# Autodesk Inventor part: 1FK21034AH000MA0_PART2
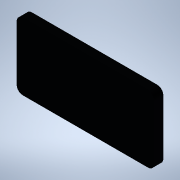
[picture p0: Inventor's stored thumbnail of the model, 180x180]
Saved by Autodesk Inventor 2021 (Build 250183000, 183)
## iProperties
Created: 2025-04
Part Number: 1FK21034AH000MA0_PART2
Material: Generic
Catalog Web Link: www.3dfindit.com
Description: -Servo synchronous motor
Document SubType Name: Modeling
Designer: psAdmin
Mass: 2.9597 g
Surface Area: 23.6483 cm^2
Volume: 2.9597 cm^3
Density: 1 g/cm^3
Appearance: PSOLRGB-38-46-56
Category: PARTsolutions
Title: 1FK21034AH000MA0_PART2
Author: Cadenas PARTsolutions
Comments: Servo synchronous motor
Sending System: PARTsolutions
Preprocessor: ST-DEVELOPER v19.3
PSOL_IDENT_0: {$CADENAS_DATA/23d-libs/siemens_ag/_cat_/ec/b7/1fk21034ah000ma0.prj},213 {VTYP=3D},{NB=1FK21034AH000
PSOL_IDENT_1: MA0_PART2},{LINA=1FK21034AH000MA0_PART2},{NN=1FK21034AH000MA0_PART2},{NOPRJ=TRUE},{DATE=19.08.2025 1
PSOL_IDENT_2: 4:01:05},{GEOMDATE=30.07.2025 02:01:02},{VERSION=},{LINEID=10},{WBVAR=},{WBNUMERIC=}  {NB=1FK21034AH
PSOL_IDENT_3: 000MA0_PART2},{LINA=1FK21034AH000MA0_PART2},{KT=DUMMY},{PREVIEW=../../../_pool_/7c/50/p_d211_xx_0093
PSOL_IDENT_4: 2j.png},{DESCSHORT=SIMOTICS S-1FK2 HD, SINAMICS S210 3AC 400V-480V, 1.01 Nm, 4500 rpm},{DESCLONG=SIM
PSOL_IDENT_5: OTICS S-1FK2 HD servo motor M0=1.27 Nm; PN = 0.48 kW at nN=4500 rpm (380-480 V); PN = 0.3 kW at nN=2
PSOL_IDENT_6: 500 rpm (200-240 V); degree of protection IP64; cylindrical shaft D14 x 30 mm; absolute encoder 22-b
PSOL_IDENT_7: it + 12-bit multiturn (encoder AM22DQC); with OCC interface; plug size M17, rotatable; SIMOTICS S-1F
PSOL_IDENT_8: K2 servomotorfor a wide range of uses in industrial environments. SIMOTICS S‑1FK2 servomotors are co
PSOL_IDENT_9: mpact synchronous motors with a high dynamic performance that set themselves apart as a result of th
PSOL_IDENT_10: eir high power density, degree of protection and overload capability. The motors are available in tw
PSOL_IDENT_11: o variants: as High Dynamic variant (highest dynamic performance as a result of the low intrinsic mo
PSOL_IDENT_12: ment of inertia for applications demanding a high dynamic performance with low moved masses) - and a
PSOL_IDENT_13: s Compact variant (precise and stable closed-loop control for medium up to large moved masses as a r
PSOL_IDENT_14: esult of a medium intrinsic moment of inertia). SIMOTICSS‑1FK2 servomotors fully exploit their stren
PSOL_IDENT_15: gths in a system with the SINAMICSS210 frequency converter and simple connection using the one cable
PSOL_IDENT_16: connection (OCC). Advantages include the short control and positioning times, fast and precise corr
PSOL_IDENT_17: ection of disturbing quantities as well as stable control with a high dynamic performance. The servo
PSOL_IDENT_18: motors can be configured to address a wide range of requirements. For example with and without hold
PSOL_IDENT_19: ing brake, IP64 or IP65 degree of protection, singleturn or multiturn absolute encoders - to name ju
PSOL_IDENT_20: st a few. Further, the servomotors are available in different shaft heights extending from 20 to 100
PSOL_IDENT_21: . A shaft sealing ring is available to achieve an IP65 degree of protection and for subsequent mount
PSOL_IDENT_22: ing at the motor or as spare part. SIMOTICS - the optimum motor for each and every motion control ap
PSOL_IDENT_23: plication.},{INTNO=4034106444822},{SUPPLIERALTNO=1FK2103-4AH00-0MA0},{MANUID=1FK21034AH000MA0},{MANU
PSOL_IDENT_24: NAME=Siemens},{MANUTYPEDESC=SYNCHRONOUS MOTOR 1FK2 HD 1,27 NM},{AAU732=SIMOTICS},{AAO057=S-1FK2},{AA
PSOL_IDENT_25: U734=SIMOTICS S-1FK2 HD servo motor M0=1.27 Nm; PN = 0.48 kW at nN=4500 rpm (380-480 V); PN = 0.3 kW
PSOL_IDENT_26: at nN=2500 rpm (200-240 V); degree of protection IP64; cylindrical shaft D14 x 30 mm; absolute enco
PSOL_IDENT_27: der 22-bit + 12-bit multiturn (encoder AM22DQC); with OCC interface; plug size M17, rotatable;},{AAW
PSOL_IDENT_28: 338=SYNCHRONOUS MOTOR 1FK2 HD 1,27 NM},{AAO742=SIMOTICS},{AAO663=4034106444822},{NOCUPEROU=1},{PRICE
PSOL_IDENT_29: QUANTITY=1},{QUANTITYMIN=1},{QUANTITYINT=1},{CTN=85015100},{COO=RO},{AAO676=1FK2103-4AH00-0MA0},{AAO
PSOL_IDENT_30: 677=Siemens AG},{ORDERUNIT=C62},{CONTENTUNIT=C62}
NB: 1FK21034AH000MA0_PART2
NT: Servo synchronous motor
NBSYN: $MANUID._PART2
LINA: 1FK21034AH000MA0_PART2
CATALOG: SIEMENS
PREVIEW: ../../../_pool_/7c/50/p_d211_xx_00932j.png
DESCSHORT: SIMOTICS S-1FK2 HD, SINAMICS S210 3AC 400V-480V, 1.01 Nm, 4500 rpm
DESCLONG: SIMOTICS S-1FK2 HD servo motor M0=1.27 Nm; PN = 0.48 kW at nN=4500 rpm (380-480 V); PN = 0.3 kW at nN=2500 rpm (200-240 V); degree of protection IP64; cylindric
INTNO: 4034106444822
SUPPLIERALTNO: 1FK2103-4AH00-0MA0
MANUID: 1FK21034AH000MA0
MANUNAME: Siemens
MANUTYPEDESC: SYNCHRONOUS MOTOR 1FK2 HD 1,27 NM
AAU732: SIMOTICS
AAO057: S-1FK2
AAU734: SIMOTICS S-1FK2 HD servo motor M0=1.27 Nm; PN = 0.48 kW at nN=4500 rpm (380-480 V); PN = 0.3 kW at nN=2500 rpm (200-240 V); degree of protection IP64; cylindric
AAW338: SYNCHRONOUS MOTOR 1FK2 HD 1,27 NM
AAO742: SIMOTICS
AAO663: 4034106444822.0
NOCUPEROU: 1
PRICEQUANTITY: 1
QUANTITYMIN: 1
QUANTITYINT: 1
CTN: 85015100
COO: RO
ARTICLENO: 1FK21034AH000MA0_PART2
BOMINFO: 1FK21034AH000MA0_PART2
CREATOR: CADENAS GmbH
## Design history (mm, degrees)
feature "2025_04_17_15_01_37_0189"
body "Solid1"
